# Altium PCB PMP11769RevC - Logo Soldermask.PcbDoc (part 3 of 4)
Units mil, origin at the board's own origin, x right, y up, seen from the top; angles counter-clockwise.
Board outline 7800 x 8510 mil, 4 copper layers (Top, Inner Top, Inner Bottom, Bottom), stack 33.235 mil thick; 451 components, 226 nets, 1199 pads, 1742 vias.
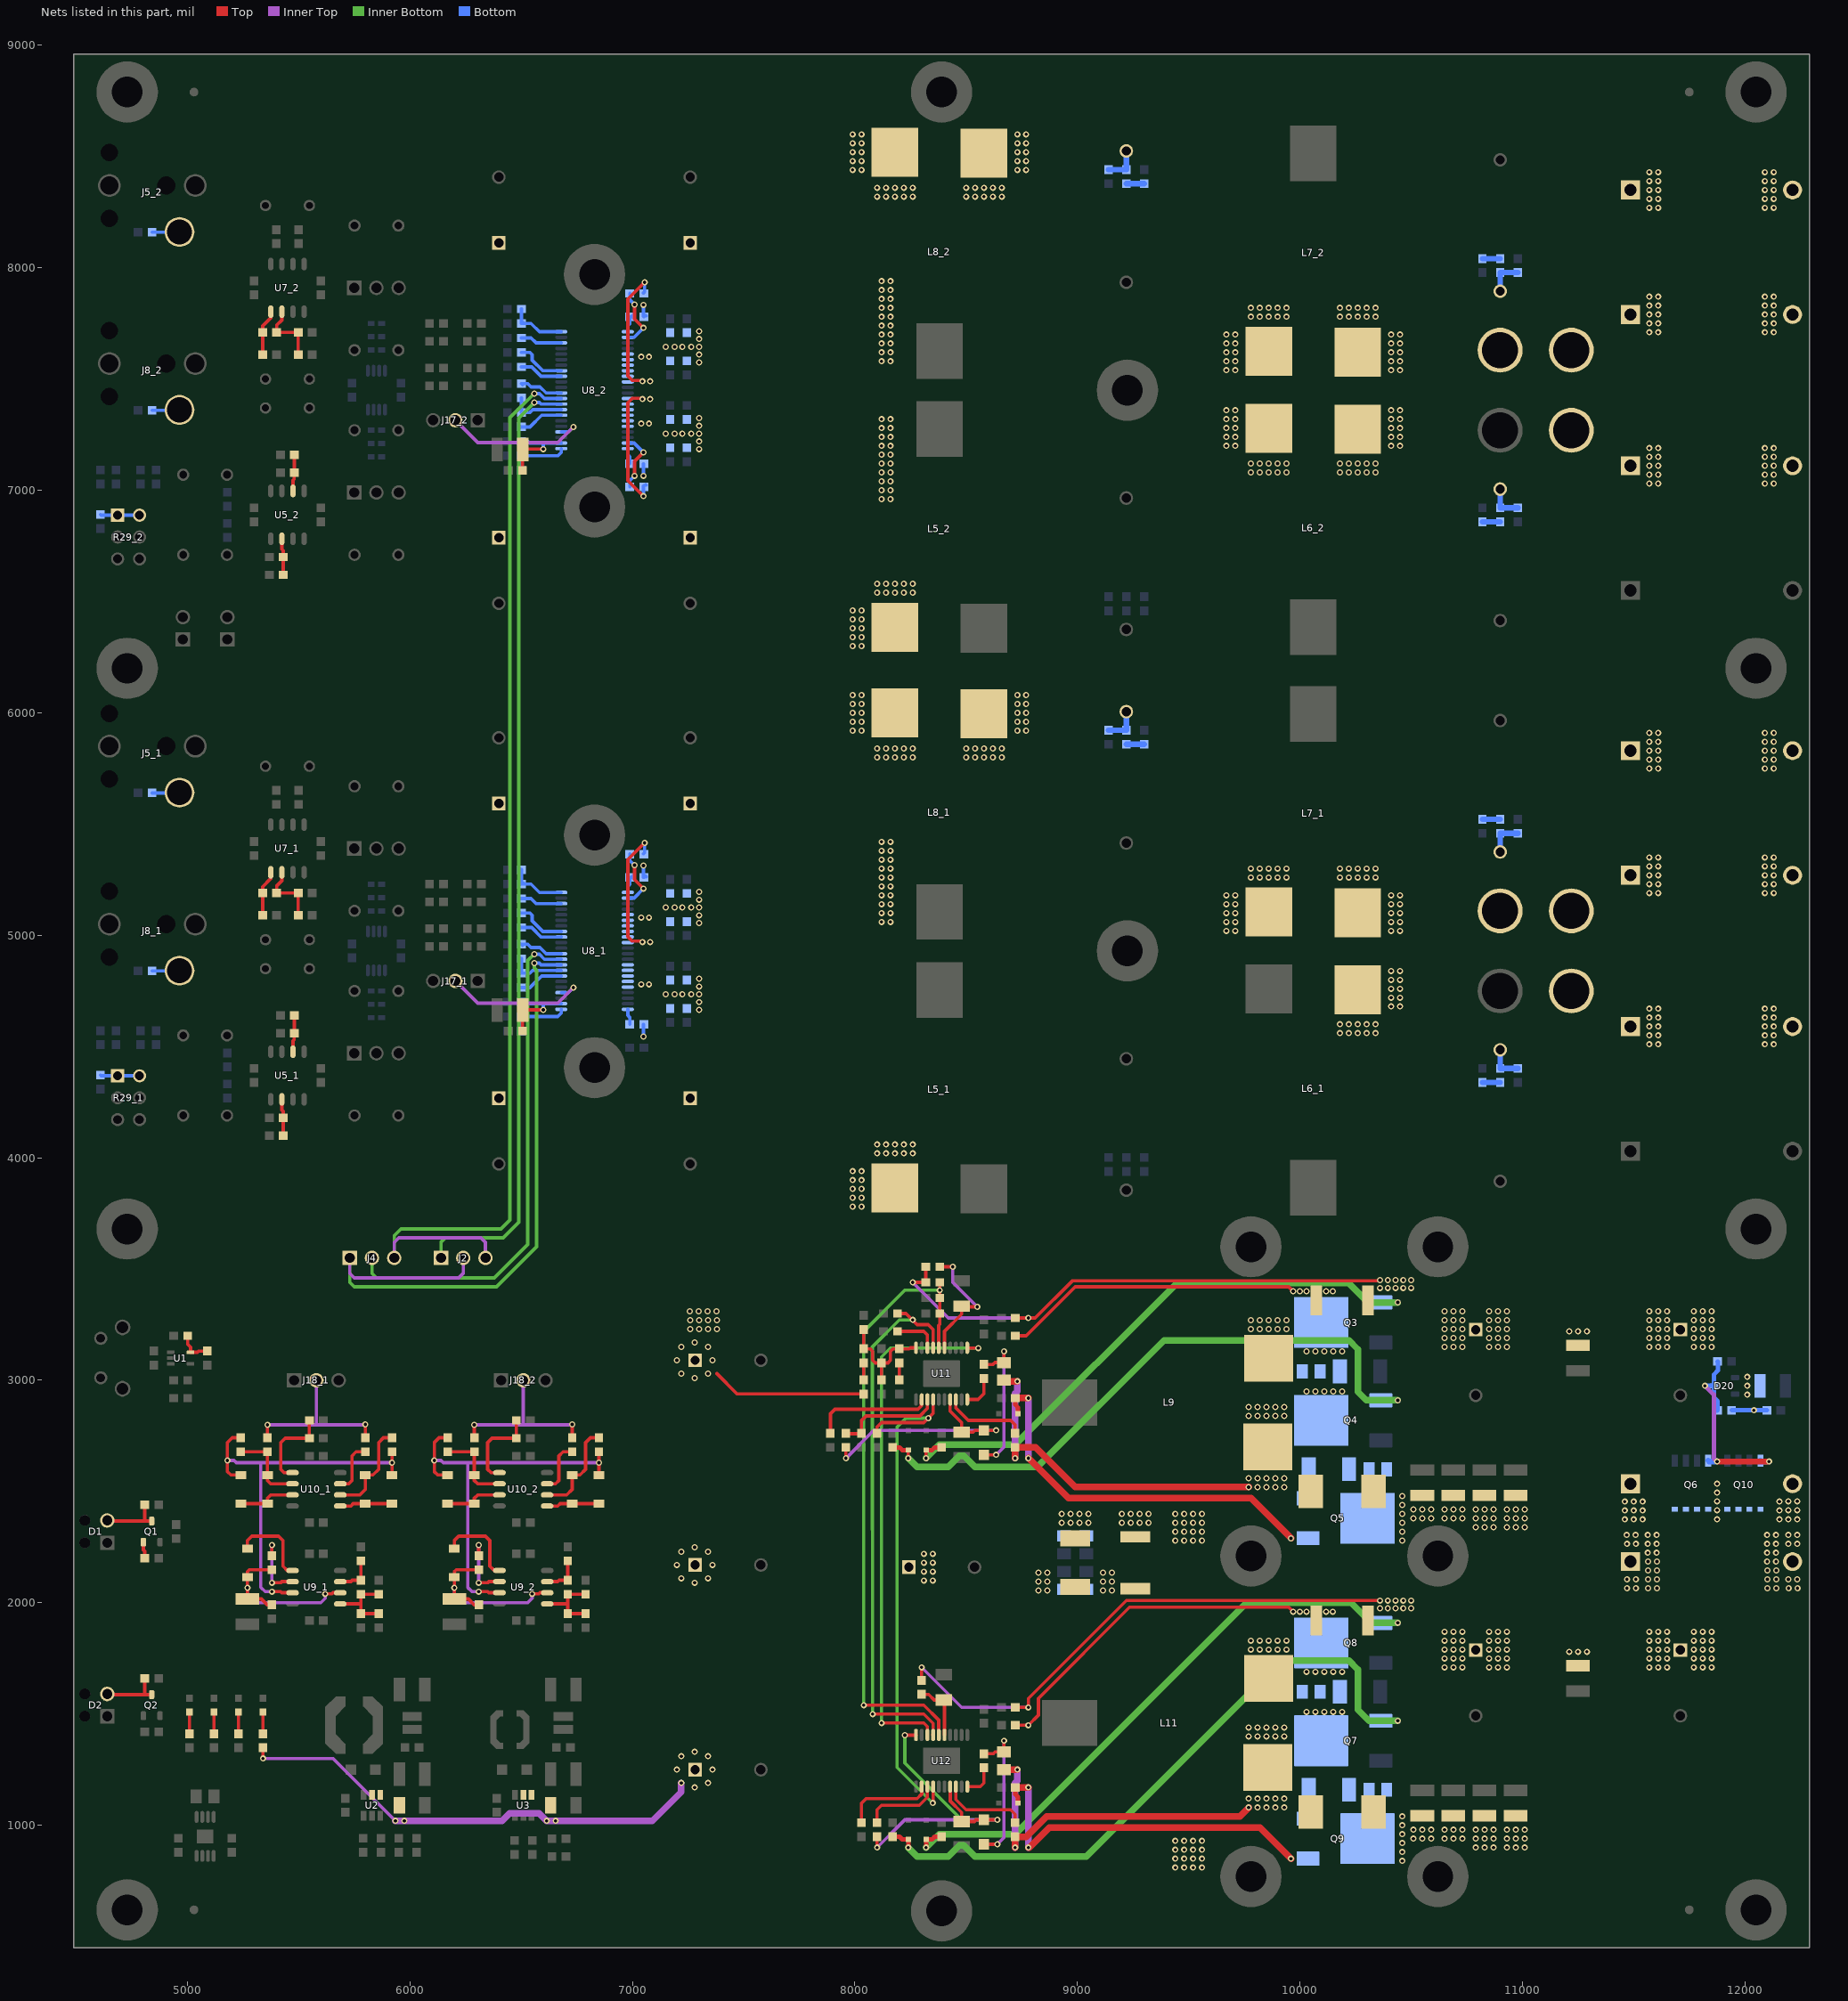
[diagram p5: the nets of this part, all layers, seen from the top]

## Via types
v1: diameter 28, hole 15, Top to Bottom, 1742 vias

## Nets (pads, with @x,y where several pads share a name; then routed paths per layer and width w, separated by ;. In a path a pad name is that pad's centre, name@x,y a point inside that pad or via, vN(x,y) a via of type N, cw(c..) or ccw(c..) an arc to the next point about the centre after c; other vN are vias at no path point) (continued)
NetC54_2_1: C54_2.1 U8_2.43 | length 268.5
  Top w15: v1(7010,7065) 7010,7130 v1(7050,7170)
  Bottom w15: U8_2.43@6979.61,7212.5 7007.5,7212.5 v1(7050,7170) ; C54_2.1@6988.5,7015 6988.5,7043.5 v1(7010,7065)
NetC54_2_2: C54_2.2 L6_2.2 U8_2.35 | length 576.3
  Top w15: v1(7050,6973.7) 6980,7043.7 6980,7393.7 7000,7413.7 v1@7050,7413.7
  Bottom w15: v1(7050,6973.7) 7050,7018.5 C54_2.2@7051.5,7020 ; C54_2.2@7060,7025.2 C54_2.2@7061.5,7023.7
  other v1: 8120,6960 8160,6960 8120,7000 8160,7000 8120,7040 8160,7040 8120,7080 8160,7080 9780,7080 9820,7080 9860,7080 9900,7080 9940,7080 8120,7120 8160,7120 9780,7120 9820,7120 9860,7120 9900,7120 9940,7120 8120,7160 8160,7160 8120,7200 8160,7200 9670,7200 9710,7200 8120,7240 8160,7240 9670,7240 9710,7240 8120,7280 8160,7280 9670,7280 9710,7280 8120,7320 8160,7320 9670,7320 9710,7320 9670,7360 9710,7360 7045,7410 7080,7410
NetC55_1_1: C55_1.1 U8_1.44 | length 71.2
  Bottom w15: U8_1.44@6979.61,4667.5 6979.61,4640.39 6988.5,4631.5 C55_1.1@6988.5,4600
NetC55_1_2: C55_1.2 L5_1.1 U8_1.39 U8_1.40 | length 53.5
  Bottom w15: v1(7050,4545) C55_1.2@7050,4598.5
  other v1: 7990,3780 8030,3780 7990,3820 8030,3820 7990,3860 8030,3860 7990,3900 8030,3900 7990,3940 8030,3940 8100,4020 8140,4020 8180,4020 8220,4020 8260,4020 8100,4060 8140,4060 8180,4060 8220,4060 8260,4060 7040,4780 7075,4780
NetC55_2_1: C55_2.1 U8_2.44 | length 71.2
  Bottom w15: U8_2.44@6979.61,7187.5 6979.61,7160.39 6988.5,7151.5 C55_2.1@6988.5,7120
NetC55_2_2: C55_2.2 L5_2.1 U8_2.39 U8_2.40 | length 53.5
  Bottom w15: v1(7050,7065) C55_2.2@7050,7118.5
  other v1: 7990,6300 8030,6300 7990,6340 8030,6340 7990,6380 8030,6380 7990,6420 8030,6420 7990,6460 8030,6460 8100,6540 8140,6540 8180,6540 8220,6540 8260,6540 8100,6580 8140,6580 8180,6580 8220,6580 8260,6580 7040,7300 7075,7300
NetC58_1_1: C58_1.1 U8_1.11 | length 203.6
  Bottom w15: C58_1.1@6506.5,4955 C58_1.1@6501.5,4960 6530.02,4960 6545.02,4945 6585,4945 6612.5,4917.5 U8_1.11@6680.39,4917.5
NetC58_2_1: C58_2.1 U8_2.11 | length 203.6
  Bottom w15: C58_2.1@6506.5,7475 C58_2.1@6501.5,7480 6530.02,7480 6545.02,7465 6585,7465 6612.5,7437.5 U8_2.11@6680.39,7437.5
NetC59_1_1: C59_1.1 U8_1.14 | length 196.9
  Bottom w15: C59_1.1@6501.5,5035 6547.65,5035 6590.15,4992.5 U8_1.14@6680.39,4992.5 U8_1.14@6680.39,4992.87
NetC59_2_1: C59_2.1 U8_2.14 | length 196.9
  Bottom w15: C59_2.1@6501.5,7555 6547.65,7555 6590.15,7512.5 U8_2.14@6680.39,7512.5 U8_2.14@6680.39,7512.87
NetC60_1_2: C60_1.2 R46_1.1 U8_1.1 | length 271.1
  Bottom w15: R46_1.1@6501.5,4570 C60_1.2@6501.5,4635 C60_1.2@6511.5,4635 ; C60_1.2@6511.5,4638.7 C60_1.2@6511.5,4635 ; U8_1.1@6680.39,4667.5 6680.39,4650.39 6665,4635 C60_1.2@6511.5,4635
NetC60_2_2: C60_2.2 R46_2.1 U8_2.1 | length 271.1
  Bottom w15: R46_2.1@6501.5,7090 C60_2.2@6501.5,7155 C60_2.2@6511.5,7155 ; C60_2.2@6511.5,7158.7 C60_2.2@6511.5,7155 ; U8_2.1@6680.39,7187.5 6680.39,7170.39 6665,7155 C60_2.2@6511.5,7155
NetC61_1_1: C61_1.1 C62_1.1 C63_1.1 J11_1.1 J12_1.1 J12_1.2 L6_1.1 | length 163.8
  Bottom w25: C62_1.1@10900,4485.28 C61_1.1@10900,4401.5 C63_1.1@10980,4401.5
  other v1: 11570,4510 11610,4510 12090,4510 12130,4510 11570,4550 11610,4550 12090,4550 12130,4550 10180,4560 10220,4560 10260,4560 10300,4560 10340,4560 11570,4590 11610,4590 12090,4590 12130,4590 10180,4600 10220,4600 10260,4600 10300,4600 10340,4600 11570,4630 11610,4630 12090,4630 12130,4630 11570,4670 11610,4670 12090,4670 12130,4670 10410,4680 10450,4680 10410,4720 10450,4720 10410,4760 10450,4760 10410,4800 10450,4800 10410,4840 10450,4840
NetC61_1_2: C61_1.2 R47_1.2 | length 80
  Bottom w25: R47_1.2@10820,4338.5 C61_1.2@10900,4338.5
NetC61_2_1: C61_2.1 C62_2.1 C63_2.1 J11_2.1 J12_2.1 J12_2.2 L6_2.1 | length 163.8
  Bottom w25: C62_2.1@10900,7005.28 C61_2.1@10900,6921.5 C63_2.1@10980,6921.5
  other v1: 11570,7030 11610,7030 12090,7030 12130,7030 11570,7070 11610,7070 12090,7070 12130,7070 10180,7080 10220,7080 10260,7080 10300,7080 10340,7080 11570,7110 11610,7110 12090,7110 12130,7110 10180,7120 10220,7120 10260,7120 10300,7120 10340,7120 11570,7150 11610,7150 12090,7150 12130,7150 11570,7190 11610,7190 12090,7190 12130,7190 10410,7200 10450,7200 10410,7240 10450,7240 10410,7280 10450,7280 10410,7320 10450,7320 10410,7360 10450,7360
NetC61_2_2: C61_2.2 R47_2.2 | length 80
  Bottom w25: R47_2.2@10820,6858.5 C61_2.2@10900,6858.5
NetC64_1_1: C64_1.1 L7_1.1 U8_1.32 | length 581.2
  Top w15: v1@7050,4973.7 7000,4973.7 6980,4993.7 6980,5340 v1(7055,5415)
  Bottom w15: C64_1.1@7050,5366.5 7055,5371.5 v1(7055,5415)
  other v1: 7045,4970 7080,4970 9670,5020 9710,5020 8120,5060 8160,5060 9670,5060 9710,5060 8120,5100 8160,5100 9670,5100 9710,5100 8120,5140 8160,5140 9670,5140 9710,5140 8120,5180 8160,5180 9670,5180 9710,5180 8120,5220 8160,5220 8120,5260 8160,5260 9780,5260 9820,5260 9860,5260 9900,5260 9940,5260 8120,5300 8160,5300 9780,5300 9820,5300 9860,5300 9900,5300 9940,5300 8120,5340 8160,5340 8120,5380 8160,5380 8120,5420 8160,5420
NetC64_1_2: C64_1.2 U8_1.24 | length 268.5
  Top w15: v1(7010,5315) 7010,5250 v1(7050,5210)
  Bottom w15: U8_1.24@6979.61,5167.5 7007.5,5167.5 v1(7050,5210) ; C64_1.2@6988.5,5365 6988.5,5336.5 v1(7010,5315)
NetC64_2_1: C64_2.1 L7_2.1 U8_2.32 | length 581.2
  Top w15: v1@7050,7493.7 7000,7493.7 6980,7513.7 6980,7860 v1(7055,7935)
  Bottom w15: C64_2.1@7050,7886.5 7055,7891.5 v1(7055,7935)
  other v1: 7045,7490 7080,7490 9670,7540 9710,7540 8120,7580 8160,7580 9670,7580 9710,7580 8120,7620 8160,7620 9670,7620 9710,7620 8120,7660 8160,7660 9670,7660 9710,7660 8120,7700 8160,7700 9670,7700 9710,7700 8120,7740 8160,7740 8120,7780 8160,7780 9780,7780 9820,7780 9860,7780 9900,7780 9940,7780 8120,7820 8160,7820 9780,7820 9820,7820 9860,7820 9900,7820 9940,7820 8120,7860 8160,7860 8120,7900 8160,7900 8120,7940 8160,7940
NetC64_2_2: C64_2.2 U8_2.24 | length 268.5
  Top w15: v1(7010,7835) 7010,7770 v1(7050,7730)
  Bottom w15: U8_2.24@6979.61,7687.5 7007.5,7687.5 v1(7050,7730) ; C64_2.2@6988.5,7885 6988.5,7856.5 v1(7010,7835)
NetC65_1_1: C65_1.1 L8_1.2 U8_1.27 U8_1.28 | length 56.4
  Bottom w15: v1(7050,5313.7) 7050,5261.5 C65_1.1@7051.5,5260 ; C65_1.1@7060,5265.2 C65_1.1@7061.5,5263.7
  other v1: 7040,5080 7075,5080 8100,5800 8140,5800 8180,5800 8220,5800 8260,5800 8100,5840 8140,5840 8180,5840 8220,5840 8260,5840 7990,5920 8030,5920 7990,5960 8030,5960 7990,6000 8030,6000 7990,6040 8030,6040 7990,6080 8030,6080
NetC65_1_2: C65_1.2 U8_1.23 | length 83.8
  Bottom w15: U8_1.23@6979.61,5192.5 6979.61,5219.61 6988.5,5228.5 C65_1.2@6988.5,5260 ; C65_1.2@6989.61,5254.8 C65_1.2@6998.5,5263.7
NetC65_2_1: C65_2.1 L8_2.2 U8_2.27 U8_2.28 | length 56.4
  Bottom w15: v1(7050,7833.7) 7050,7781.5 C65_2.1@7051.5,7780 ; C65_2.1@7060,7785.2 C65_2.1@7061.5,7783.7
  other v1: 7040,7600 7075,7600 8100,8320 8140,8320 8180,8320 8220,8320 8260,8320 8100,8360 8140,8360 8180,8360 8220,8360 8260,8360 7990,8440 8030,8440 7990,8480 8030,8480 7990,8520 8030,8520 7990,8560 8030,8560 7990,8600 8030,8600
NetC65_2_2: C65_2.2 U8_2.23 | length 83.8
  Bottom w15: U8_2.23@6979.61,7712.5 6979.61,7739.61 6988.5,7748.5 C65_2.2@6988.5,7780 ; C65_2.2@6989.61,7774.8 C65_2.2@6998.5,7783.7
NetC66_1_2: C66_1.2 C67_1.1 R48_1.1 U8_1.2 | length 396.8
  Top w15: R48_1.1@6506.5,4570 6507.09,4570.59 C67_1.1@6507.09,4663.54 6508.54,4665 v1(6600,4665)
  Bottom w15: C66_1.2@6501.5,4700 6531.02,4700 6538.52,4692.5 6600,4692.5 ; v1(6600,4665) 6600,4692.5 ; U8_1.2@6680.39,4692.5 6600,4692.5
NetC66_2_2: C66_2.2 C67_2.1 R48_2.1 U8_2.2 | length 396.8
  Top w15: R48_2.1@6506.5,7090 6507.09,7090.59 C67_2.1@6507.09,7183.54 6508.54,7185 v1(6600,7185)
  Bottom w15: C66_2.2@6501.5,7220 6531.02,7220 6538.52,7212.5 6600,7212.5 ; v1(6600,7185) 6600,7212.5 ; U8_2.2@6680.39,7212.5 6600,7212.5
NetC68_1_1: C68_1.1 C69_1.1 C70_1.1 J13_1.1 J13_1.2 J14_1.1 L7_1.2 | length 163.8
  Bottom w25: C69_1.1@10900,5374.72 C68_1.1@10900,5458.5 C70_1.1@10980,5458.5
  other v1: 10410,5020 10450,5020 10410,5060 10450,5060 10410,5100 10450,5100 10410,5140 10450,5140 10410,5180 10450,5180 11570,5190 11610,5190 12090,5190 12130,5190 11570,5230 11610,5230 12090,5230 12130,5230 10180,5260 10220,5260 10260,5260 10300,5260 10340,5260 11570,5270 11610,5270 12090,5270 12130,5270 10180,5300 10220,5300 10260,5300 10300,5300 10340,5300 11570,5310 11610,5310 12090,5310 12130,5310 11570,5350 11610,5350 12090,5350 12130,5350
NetC68_1_2: C68_1.2 R50_1.2 | length 80
  Bottom w25: R50_1.2@10820,5521.5 C68_1.2@10900,5521.5
NetC68_2_1: C68_2.1 C69_2.1 C70_2.1 J13_2.1 J13_2.2 J14_2.1 L7_2.2 | length 163.8
  Bottom w25: C69_2.1@10900,7894.72 C68_2.1@10900,7978.5 C70_2.1@10980,7978.5
  other v1: 10410,7540 10450,7540 10410,7580 10450,7580 10410,7620 10450,7620 10410,7660 10450,7660 10410,7700 10450,7700 11570,7710 11610,7710 12090,7710 12130,7710 11570,7750 11610,7750 12090,7750 12130,7750 10180,7780 10220,7780 10260,7780 10300,7780 10340,7780 11570,7790 11610,7790 12090,7790 12130,7790 10180,7820 10220,7820 10260,7820 10300,7820 10340,7820 11570,7830 11610,7830 12090,7830 12130,7830 11570,7870 11610,7870 12090,7870 12130,7870
NetC68_2_2: C68_2.2 R50_2.2 | length 80
  Bottom w25: R50_2.2@10820,8041.5 C68_2.2@10900,8041.5
NetC71_1_2: C71_1.2 U8_1.15 | length 227.7
  Bottom w15: C71_1.2@6501.5,5100 6540,5100 6550,5090 6550,5065 6597.5,5017.5 U8_1.15@6680.39,5017.5
NetC71_2_2: C71_2.2 U8_2.15 | length 227.7
  Bottom w15: C71_2.2@6501.5,7620 6540,7620 6550,7610 6550,7585 6597.5,7537.5 U8_2.15@6680.39,7537.5
NetC72_1_2: C72_1.2 R51_1.1 U8_1.22 | length 259.4
  Bottom w15: R51_1.1@6501.5,5295 C72_1.2@6501.5,5230 6545,5230 6582.5,5192.5 U8_1.22@6680.39,5192.5
NetC72_2_2: C72_2.2 R51_2.1 U8_2.22 | length 259.4
  Bottom w15: R51_2.1@6501.5,7815 C72_2.2@6501.5,7750 6545,7750 6582.5,7712.5 U8_2.22@6680.39,7712.5
NetC73_1_1: C73_1.1 U8_1.20 | length 188.2
  Bottom w15: C73_1.1@6501.5,5165 6545,5165 6567.5,5142.5 U8_1.20@6680.39,5142.5
NetC73_2_1: C73_2.1 U8_2.20 | length 188.2
  Bottom w15: C73_2.1@6501.5,7685 6545,7685 6567.5,7662.5 U8_2.20@6680.39,7662.5
NetC74_1_1: C74_1.1 C75_1.1 C76_1.1 J15_1.1 J16_1.1 J16_1.2 L8_1.1 | length 163.8
  Bottom w25: C76_1.1@9140,5921.5 C74_1.1@9220,5921.5 C75_1.1@9220,6005.28
  other v1: 11570,5750 11610,5750 12090,5750 12130,5750 11570,5790 11610,5790 12090,5790 12130,5790 8500,5800 8540,5800 8580,5800 8620,5800 8660,5800 11570,5830 11610,5830 12090,5830 12130,5830 8500,5840 8540,5840 8580,5840 8620,5840 8660,5840 11570,5870 11610,5870 12090,5870 12130,5870 11570,5910 11610,5910 12090,5910 12130,5910 8730,5920 8770,5920 8730,5960 8770,5960 8730,6000 8770,6000 8730,6040 8770,6040 8730,6080 8770,6080
NetC74_1_2: C74_1.2 R52_1.2 | length 80
  Bottom w25: C74_1.2@9220,5858.5 R52_1.2@9300,5858.5
NetC74_2_1: C74_2.1 C75_2.1 C76_2.1 J15_2.1 J16_2.1 J16_2.2 L8_2.1 | length 163.8
  Bottom w25: C76_2.1@9140,8441.5 C74_2.1@9220,8441.5 C75_2.1@9220,8525.28
  other v1: 11570,8270 11610,8270 12090,8270 12130,8270 11570,8310 11610,8310 12090,8310 12130,8310 8500,8320 8540,8320 8580,8320 8620,8320 8660,8320 11570,8350 11610,8350 12090,8350 12130,8350 8500,8360 8540,8360 8580,8360 8620,8360 8660,8360 11570,8390 11610,8390 12090,8390 12130,8390 11570,8430 11610,8430 12090,8430 12130,8430 8730,8440 8770,8440 8730,8480 8770,8480 8730,8520 8770,8520 8730,8560 8770,8560 8730,8600 8770,8600
NetC74_2_2: C74_2.2 R52_2.2 | length 80
  Bottom w25: C74_2.2@9220,8378.5 R52_2.2@9300,8378.5
NetC79_1_1: C79_1.1 D11_1.1 R56_1.1 R60_1.2 U9_1.6 | length 862.5
  Top w15: R60_1.2@5380,1991.5 5358.5,1991.5 5332.91,2017.09 C79_1.1@5270,2017.09 v1(5270,2067.22) D11_1.1@5270,2115.53 5270,2140 5278.5,2148.5 R56_1.1@5380,2148.5 ; v1(5620,2040) 5650,2040 5655,2045 U9_1.6@5687.28,2045
  Inner Top w15: v1(5270,2067.22) 5270,2020 5290,2000 5600,2000 5620,2020 v1(5620,2040) v1@5618.33,2041.67
NetC79_2_1: C79_2.1 D11_2.1 R56_2.1 R60_2.2 U9_2.6 | length 862.5
  Top w15: R60_2.2@6310,1991.5 6288.5,1991.5 6262.91,2017.09 C79_2.1@6200,2017.09 v1(6200,2067.22) D11_2.1@6200,2115.53 6200,2140 6208.5,2148.5 R56_2.1@6310,2148.5 ; v1(6550,2040) 6580,2040 6585,2045 U9_2.6@6617.28,2045
  Inner Top w15: v1(6200,2067.22) 6200,2020 6220,2000 6530,2000 6550,2020 v1(6550,2040) v1@6548.33,2041.67
NetC81_1_2: C81_1.2 R57_1.1 R61_1.1 R62_1.1 U9_1.5 | length 339.7
  Top w15: U9_1.5@5687.28,1995 5780,1995 ; C81_1.2@5860,1951.5 R61_1.1@5780,1951.5 5780,1995 ; R57_1.1@5860,2038.5 R62_1.1@5780,2038.5 5780,1995
NetC81_2_2: C81_2.2 R57_2.1 R61_2.1 R62_2.1 U9_2.5 | length 339.7
  Top w15: U9_2.5@6617.28,1995 6710,1995 ; C81_2.2@6790,1951.5 R61_2.1@6710,1951.5 6710,1995 ; R57_2.1@6790,2038.5 R62_2.1@6710,2038.5 6710,1995
NetC85_2: C85.2 R74.1 | length 77
  Top w15: C85.2@8200,3001.5 R74.1@8200,3078.5
NetC88_1: C88.1 D14.1 R72.1 | length 683.1
  Top w15: D14.1@8580,2664.88 8580.12,2665 v1(8635,2665) ; R72.1@8580,3071.5 8621.5,3071.5 8630,3080 C88.1@8670,3080 v1(8670,3130)
  Inner Top w15: v1(8635,2665) 8670,2700 v1@8670,3135
NetC89_1: C89.1 D15.1 R73.1 | length 681.3
  Top w15: D15.1@8580,914.88 8580.12,915 v1(8640,915) ; R73.1@8580,1321.5 8621.5,1321.5 8630,1330 C89.1@8670,1330 v1(8670,1380)
  Inner Top w15: v1(8640,915) 8670.37,945.37 8670.37,1379.63 v1(8670,1380)
NetC90_2: C90.2 R74.2 R78.1 R85.2 R86.2 U11.10 | length 490.3
  Top w15: R86.2@8040,3228.5 R78.1@8040,3141.5 8068.5,3141.5 8080,3130 8080,3090 8091.5,3078.5 R85.2@8120,3078.5 ; C90.2@8120,3001.5 R85.2@8120,3078.5 ; 8243.5,3141.5 8171.5,3141.5 8160,3130 8160,3090 8148.5,3078.5 R85.2@8120,3078.5 ; 8251.14,3146.14 U11.10@8274.84,3146.14
NetC92_2: C92.2 R69.1 U11.5 | length 574.3
  Top w15: R69.1@8381.5,3510 v1(8440,3510) ; U11.5@8402.8,3146.14 8402.8,3219.65 8402.48,3219.96 8480,3297.48 C92.2@8480,3332.91 8482.91,3330 v1(8550,3330)
  Inner Top w15: v1(8440,3510) 8440,3440 v1(8550,3330)
NetC93_2: C93.2 R71.1 U12.5 | length 258.5
  Top w15: R71.1@8300,1588.5 8331.5,1588.5 8357.09,1562.91 C93.2@8400,1562.91 ; C93.2@8400,1552.91 8402.8,1550.12 U12.5@8402.8,1406.14
NetC95_1: C95.1 R87.2
NetC95_2: C95.2 C99.1 C100.1 C102.1 C103.1 C107.2 C111.2 C115.2 C119.1 C120.1 C122.1 C123.1 D16.1 D21.1 L10.1 Q5.4 Q9.4 R96.1
  other v1: 9440,810 9480,810 9520,810 9560,810 10460,840 9440,850 9480,850 9520,850 9560,850 10460,880 9440,890 9480,890 9520,890 9560,890 10790,900 10830,900 10870,900 10930,900 10970,900 11010,900 10460,920 9440,930 9480,930 9520,930 9560,930 10510,940 10550,940 10590,940 10650,940 10690,940 10730,940 10790,940 10830,940 10870,940 10930,940 10970,940 11010,940 10460,960 10510,980 10550,980 10590,980 10650,980 10690,980 10730,980 10790,980 10830,980 10870,980 10930,980 10970,980 11010,980 10460,1000 10460,1040 9440,2280 9480,2280 9520,2280 9560,2280 10460,2280 9440,2320 9480,2320 9520,2320 9560,2320 10460,2320 10790,2340 10830,2340 10870,2340 10930,2340 10970,2340 11010,2340 8930,2360 8970,2360 9010,2360 9050,2360 9200,2360 9240,2360 9280,2360 9320,2360 9440,2360 9480,2360 9520,2360 9560,2360 10460,2360 10510,2380 10550,2380 10590,2380 10650,2380 10690,2380 10730,2380 10790,2380 10830,2380 10870,2380 10930,2380 10970,2380 11010,2380 8930,2400 8970,2400 9010,2400 9050,2400 9200,2400 9240,2400 9280,2400 9320,2400 9440,2400 9480,2400 9520,2400 9560,2400 10460,2400 10510,2420 10550,2420 10590,2420 10650,2420 10690,2420 10730,2420 10790,2420 10830,2420 10870,2420 10930,2420 10970,2420 11010,2420 10460,2440 10460,2480
NetC96_2: C96.2 R90.2
NetC106_2: C106.2 D20.3 Q6.4 Q10.4 R89.2 | length 958.2
  Top w25: v1(11875,2635) v1(12108.5,2635)
  Inner Top w20: v1(11820,2975) 11860,2935 11860,2650 v1(11875,2635)
  Bottom w20: v1(11820,2975) D20.3@11861.26,2975 ; R89.2@11875,2863 R89.2@11877,2865 11877,2906.5 11861.26,2922.24 D20.3@11861.26,2975 ; C106.2@11877,3085 11878.5,3083.5 11878.5,3043.9 11861.26,3026.65 D20.3@11861.26,2975
  Bottom w25: Q6.4@11835,2639.3 11839.3,2635 v1(11875,2635) ; Q10.4@12068.5,2639.3 12072.8,2635 v1(12108.5,2635)
NetC111_1: C111.1 R97.2
NetC116_2: C116.2 R99.2
NetD1_2: D1.2 Q1.3 R2.1 | length 274.4
  Top w15: D1.2@4640.2,2370.2 4643.15,2367.24 4810,2367.24 ; R2.1@4808.5,2440 4808.5,2368.74 4810,2367.24 ; Q1.3@4840,2367.24 4810,2367.24
NetD2_2: D2.2 Q2.3 R8.1 | length 274.4
  Top w15: D2.2@4640.2,1590.2 4643.15,1587.24 4810,1587.24 ; R8.1@4808.5,1660 4808.5,1588.74 4810,1587.24 ; Q2.3@4840,1587.24 4810,1587.24
NetD4_2: D4.2 R12.1 | length 97
  Top w15: R12.1@5340,1411.5 D4.2@5340,1508.5
NetD5_2: D5.2 R13.1 | length 97
  Top w15: R13.1@5230,1411.5 D5.2@5230,1508.5
NetD6_1: D6.1 R14.1 | length 97
  Top w15: R14.1@5120,1411.5 D6.1@5120,1508.5
NetD7_2: D7.2 R15.1 | length 97
  Top w15: R15.1@5010,1411.5 D7.2@5010,1508.5
NetD9_1_1: D9_1.1 D10_1.2 U10_1.1 | length 237.1
  Top w15: U10_1.1@5687.28,2435 5735,2435 5745.53,2445.53 D9_1.1@5800,2445.53 D10_1.2@5920,2445.53
NetD9_1_2: D9_1.2 R55_1.2 U10_1.2 | length 447
  Top w15: U10_1.2@5687.28,2485 5774.99,2485 5800,2510.01 D9_1.2@5800,2574.47 5834.47,2574.47 5860,2600 5860,2720 5881.5,2741.5 R55_1.2@5920,2741.5
NetD9_2_1: D9_2.1 D10_2.2 U10_2.1 | length 237.1
  Top w15: U10_2.1@6617.28,2435 6665,2435 6675.53,2445.53 D9_2.1@6730,2445.53 D10_2.2@6850,2445.53
NetD9_2_2: D9_2.2 R55_2.2 U10_2.2 | length 447
  Top w15: U10_2.2@6617.28,2485 6704.99,2485 6730,2510.01 D9_2.2@6730,2574.47 6764.47,2574.47 6790,2600 6790,2720 6811.5,2741.5 R55_2.2@6850,2741.5
NetD10_1_1: D10_1.1 D13_1.1 R55_1.1 R63_1.1 U9_1.3 | length 1826.5
  Top w15: D13_1.1@5240,2574.47 5195.53,2574.47 5180,2590 v1(5180,2640) 5180,2720 5201.5,2741.5 R63_1.1@5240,2741.5 ; v1(5380,2050) 5420,2050 5425,2045 U9_1.3@5472.72,2045 ; D10_1.1@5920,2574.47 v1(5920,2630) R55_1.1@5920,2678.5
  Inner Top w15: v1(5180,2640) 5210,2640 5220.37,2629.63 5330,2629.63 ; v1(5380,2050) 5350,2050 5330,2070 5330,2629.63 ; v1(5920,2630) 5919.63,2629.63 5330,2629.63
NetD10_2_1: D10_2.1 D13_2.1 R55_2.1 R63_2.1 U9_2.3 | length 1826.5
  Top w15: D13_2.1@6170,2574.47 6125.53,2574.47 6110,2590 v1(6110,2640) 6110,2720 6131.5,2741.5 R63_2.1@6170,2741.5 ; v1(6310,2050) 6350,2050 6355,2045 U9_2.3@6402.72,2045 ; D10_2.1@6850,2574.47 v1(6850,2630) R55_2.1@6850,2678.5
  Inner Top w15: v1(6110,2640) 6140,2640 6150.37,2629.63 6260,2629.63 ; v1(6310,2050) 6280,2050 6260,2070 6260,2629.63 ; v1(6850,2630) 6849.63,2629.63 6260,2629.63
NetD11_1_2: D11_1.2 U9_1.1 | length 378.5
  Top w15: D11_1.2@5270,2244.47 5270,2280 5290,2300 5410,2300 5430,2280 5430,2164.33 5449.33,2145 U9_1.1@5472.72,2145
NetD11_2_2: D11_2.2 U9_2.1 | length 378.5
  Top w15: D11_2.2@6200,2244.47 6200,2280 6220,2300 6340,2300 6360,2280 6360,2164.33 6379.33,2145 U9_2.1@6402.72,2145
NetD12_1_1: D12_1.1 D13_1.2 U10_1.7 | length 263.4
  Top w15: D13_1.2@5240,2445.53 D12_1.1@5360,2445.53 5360,2470 5375,2485 U10_1.7@5472.72,2485
NetD12_1_2: D12_1.2 R63_1.2 R64_1.2 U10_1.6 | length 367.4
  Top w15: R63_1.2@5240,2678.5 R64_1.2@5360,2678.5 D12_1.2@5360,2574.46 5360,2550 5375,2535 U10_1.6@5472.72,2535
NetD12_2_1: D12_2.1 D13_2.2 U10_2.7 | length 263.4
  Top w15: D13_2.2@6170,2445.53 D12_2.1@6290,2445.53 6290,2470 6305,2485 U10_2.7@6402.72,2485
NetD12_2_2: D12_2.2 R63_2.2 R64_2.2 U10_2.6 | length 367.4
  Top w15: R63_2.2@6170,2678.5 R64_2.2@6290,2678.5 D12_2.2@6290,2574.46 6290,2550 6305,2535 U10_2.6@6402.72,2535
NetD17_2: D17.2 Q3.1 R93.2 | length 2594.3
  Top w15: v1(8320,2650) D17.2@8320,2686.69
  Top w20: D17.2@8320,2686.69 8347.19,2686.69 8359,2698.5 R93.2@8390,2698.5
  Inner Bottom w30: v1(8320,2650) 8380,2710 8720,2710 9447.87,3437.87 10218.9,3437.87 10306.77,3350 v1(10440,3350)
NetD18_2: D18.2 Q4.1 R94.2 | length 2829.3
  Top w15: v1(8240,2650) D18.2@8240,2686.69
  Top w20: R94.2@8170,2698.5 8201,2698.5 8212.81,2686.69 D18.2@8240,2686.69
  Inner Bottom w30: v1(8240,2650) 8280,2610 8420,2610 8470,2660 8490,2660 8540,2610 8820,2610 9390,3180 10220,3180 10260,3140 10260,2949.13 10299.13,2910 v1(10440,2910)
NetD19_2: D19.2 Q5.1 R95.2 | length 1712.5
  Top w20: R95.2@8721.5,2920 8721.5,2889 8733.31,2877.19 D19.2@8733.31,2850
  Top w30: R95.2@8721.5,2920 v1(8780,2920) ; v1(8780,2650) 8960,2470 9780,2470 v1(9960,2290)
  Inner Top w30: v1@8780,2660 v1@8780,2910
NetD22_2: D22.2 Q7.1 R102.2 | length 2951.4
  Top w20: R102.2@8170,948.5 8201,948.5 8212.81,936.69 D22.2@8240,936.69 v1(8240,900)
  Inner Bottom w30: v1(8240,900) 8280,860 8420,860 8470,910 8490,910 8540,860 9040,860 9920,1740 10220,1740 10260,1700 10260,1520 10310,1470 v1(10440,1470)
NetD23_2: D23.2 Q8.1 R103.2 | length 2724.5
  Top w20: v1(8320,900) D23.2@8320,936.69 8347.19,936.69 8359,948.5 R103.2@8390,948.5
  Inner Bottom w30: v1(8320,900) 8380,960 8720,960 9760,2000 10230,2000 10320,1910 v1(10440,1910)
NetD24_2: D24.2 Q9.1 R104.2 | length 1678.7
  Top w20: R104.2@8721.5,1170 8721.5,1139 8733.31,1127.19 D24.2@8733.31,1100
  Top w30: R104.2@8721.5,1170 v1(8780,1170) ; v1(8780,900) 8783.56,900 8873.56,990 9820,990 v1(9960,850)
  Inner Top w30: v1(8780,900) v1(8780,1170)
NetJ5_1_4: J5_1.4 R23_1.2 | length 124
  Bottom w15: R23_1.2@4841.5,5640 4963.62,5640 J5_1.4@4964.96,5641.34
NetJ5_2_4: J5_2.4 R23_2.2 | length 124
  Bottom w15: R23_2.2@4841.5,8160 4963.62,8160 J5_2.4@4964.96,8161.34
NetJ8_1_4: J8_1.4 R40_1.2 | length 124
  Bottom w15: R40_1.2@4841.5,4840 4963.62,4840 J8_1.4@4964.96,4841.34
NetJ8_2_4: J8_2.4 R40_2.2 | length 124
  Bottom w15: R40_2.2@4841.5,7360 4963.62,7360 J8_2.4@4964.96,7361.34
NetJ17_1_2: J17_1.2 U8_1.4 | length 664.3
  Inner Top w15: J17_1.2@6205,4795 6305,4695 6665,4695 v1(6735,4765)
  Bottom w15: U8_1.4@6680.39,4742.5 6712.5,4742.5 v1(6735,4765)
NetJ17_2_2: J17_2.2 U8_2.4 | length 664.3
  Inner Top w15: J17_2.2@6205,7315 6305,7215 6665,7215 v1(6735,7285)
  Bottom w15: U8_2.4@6680.39,7262.5 6712.5,7262.5 v1(6735,7285)
NetJ18_1_2: J18_1.2 R59_1.1 R64_1.1 | length 759.1
  Top w15: R64_1.1@5360,2741.5 v1(5360,2800) ; R59_1.1@5800,2741.5 v1(5800,2801.5)
  Inner Top w15: v1(5360,2800) 5580,2800 ; J18_1.2@5580,3000 5580,2800 ; v1(5800,2801.5) 5798.5,2800 5580,2800
NetJ18_2_2: J18_2.2 R59_2.1 R64_2.1 | length 759.1
  Top w15: R64_2.1@6290,2741.5 v1(6290,2800) ; R59_2.1@6730,2741.5 v1(6730,2801.5)
  Inner Top w15: v1(6290,2800) 6510,2800 ; J18_2.2@6510,3000 6510,2800 ; v1(6730,2801.5) 6728.5,2800 6510,2800
NetJ20_1: J20.1 J20.2 Q6.5 Q6.6 Q6.7 Q6.8 Q10.5 Q10.6 Q10.7 Q10.8
  other v1: 11460,2375 11500,2375 11540,2375 11875,2375 12155,2375 12195,2375 12235,2375 11460,2415 11500,2415 11540,2415 12155,2415 11875,2416.5 12195,2416.5 12235,2416.5 11460,2455 11500,2455 11540,2455 12155,2455 11875,2456.5 12195,2456.5 12235,2456.5 11875,2495 11875,2535
NetL9_2: L9.2 R88.2 R92.2 | length 1347.9
  Top w15: R92.2@8721.5,3200 8770,3200 8990,3420 9950,3420 v1(9970,3400)
  other v1: 9780,3230 9820,3230 9860,3230 9900,3230 9940,3230 9780,3270 9820,3270 9860,3270 9900,3270 9940,3270 10000,3400 10030,3400 10118,3400 10148,3400
NetL11_2: L11.2 R98.2 R101.2 | length 1510.5
  Top w15: R101.2@8721.5,1450 v1@8770,1450 ; v1(8780,1450) 8824.82,1494.82 8824.82,1570.31 9234.52,1980 9950,1980 v1(9970,1960)
  other v1: 9780,1790 9820,1790 9860,1790 9900,1790 9940,1790 9780,1830 9820,1830 9860,1830 9900,1830 9940,1830 10000,1960 10030,1960 10118,1960 10148,1960
NetQ1_1: Q1.1 R4.2 | length 75.2
  Top w15: Q1.1@4802.6,2272.76 4802.6,2237.4 4808.5,2231.5 R4.2@4808.5,2200
NetR5_1: R5.1 R6.2 U1.5 | length 157.9
  Top w15: R6.2@5001.5,3200 5001.5,3161.65 5014.29,3148.86 U1.5@5014.29,3125.59 5045.59,3125.59 5051.5,3131.5 R5.1@5090,3131.5
NetR25_1_1: R25_1.1 R28_1.2 R33_1.2 U7_1.2 | length 299.5
  Top w15: U7_1.2@5425,5282.72 5425,5245 5401.5,5221.5 R25_1.1@5401.5,5190 R33_1.2@5498.5,5190 R28_1.2@5498.5,5090
NetR25_1_2: R25_1.2 R35_1.1 U7_1.1 | length 207.8
  Top w15: R35_1.1@5338.5,5090 R25_1.2@5338.5,5190 5338.5,5218.5 5375,5255 U7_1.1@5375,5282.72
NetR25_2_1: R25_2.1 R28_2.2 R33_2.2 U7_2.2 | length 299.5
  Top w15: U7_2.2@5425,7802.72 5425,7765 5401.5,7741.5 R25_2.1@5401.5,7710 R33_2.2@5498.5,7710 R28_2.2@5498.5,7610
NetR25_2_2: R25_2.2 R35_2.1 U7_2.1 | length 207.8
  Top w15: R35_2.1@5338.5,7610 R25_2.2@5338.5,7710 5338.5,7738.5 5375,7775 U7_2.1@5375,7802.72
NetR29_1_1: R29_1.1 R29_1.1' R32_1.2 | length 176.5
  Bottom w15: R32_1.2@4610,4371.5 4613.07,4368.43 R29_1.1@4686.85,4368.43 R29_1.1'@4785.28,4368.43
NetR29_2_1: R29_2.1 R29_2.1' R32_2.2 | length 176.5
  Bottom w15: R32_2.2@4610,6891.5 4613.07,6888.43 R29_2.1@4686.85,6888.43 R29_2.1'@4785.28,6888.43
NetR30_1_1: R30_1.1 R31_1.1 U5_1.2 | length 165.4
  Top w15: U5_1.2@5425,4262.72 5425,4215 5431.5,4208.5 R31_1.1@5431.5,4180 R30_1.1@5431.5,4100
NetR30_2_1: R30_2.1 R31_2.1 U5_2.2 | length 165.4
  Top w15: U5_2.2@5425,6782.72 5425,6735 5431.5,6728.5 R31_2.1@5431.5,6700 R30_2.1@5431.5,6620
NetR43_1_1: R43_1.1 R44_1.1 U5_1.6 | length 165.4
  Top w15: U5_1.6@5475,4477.28 5475,4525 5480,4530 5480,4558.5 R44_1.1@5481.5,4560 R43_1.1@5481.5,4640
NetR43_2_1: R43_2.1 R44_2.1 U5_2.6 | length 165.4
  Top w15: U5_2.6@5475,6997.28 5475,7045 5480,7050 5480,7078.5 R44_2.1@5481.5,7080 R43_2.1@5481.5,7160
NetR49_1_2: R49_1.2 U8_1.7 | length 200.6
  Bottom w15: R49_1.2@6501.5,4765 6540,4765 6592.5,4817.5 U8_1.7@6680.39,4817.5
NetR49_2_2: R49_2.2 U8_2.7 | length 200.6
  Bottom w15: R49_2.2@6501.5,7285 6540,7285 6592.5,7337.5 U8_2.7@6680.39,7337.5
NetR53_1_2: R53_1.2 R54_1.2 U8_1.8 | length 249.1
  Bottom w15: R54_1.2@6501.5,4895 R53_1.2@6501.5,4830 6540,4830 6552.5,4842.5 U8_1.8@6680.39,4842.5
NetR53_2_2: R53_2.2 R54_2.2 U8_2.8 | length 249.1
  Bottom w15: R54_2.2@6501.5,7415 R53_2.2@6501.5,7350 6540,7350 6552.5,7362.5 U8_2.8@6680.39,7362.5
NetR56_1_2: R56_1.2 U9_1.2 | length 313.3
  Top w15: v1(5380,2090) 5420,2090 5425,2095 U9_1.2@5472.72,2095 ; R56_1.2@5380,2211.5 v1(5380,2260)
  Inner Top w15: v1(5380,2090) v1(5380,2260)
NetR56_2_2: R56_2.2 U9_2.2 | length 313.3
  Top w15: v1(6310,2090) 6350,2090 6355,2095 U9_2.2@6402.72,2095 ; R56_2.2@6310,2211.5 v1(6310,2260)
  Inner Top w15: v1(6310,2090) v1(6310,2260)
NetR58_1_1: R58_1.1 R62_1.2 U9_1.7 | length 182.4
  Top w15: U9_1.7@5687.28,2095 5735,2095 5741.5,2101.5 R62_1.2@5780,2101.5 R58_1.1@5780,2188.5
NetR58_2_1: R58_2.1 R62_2.2 U9_2.7 | length 182.4
  Top w15: U9_2.7@6617.28,2095 6665,2095 6671.5,2101.5 R62_2.2@6710,2101.5 R58_2.1@6710,2188.5
NetR59_1_2: R59_1.2 U10_1.3 | length 236.6
  Top w15: U10_1.3@5687.28,2535 5725,2535 5740,2550 5740,2660 5758.5,2678.5 R59_1.2@5800,2678.5
NetR59_2_2: R59_2.2 U10_2.3 | length 236.6
  Top w15: U10_2.3@6617.28,2535 6655,2535 6670,2550 6670,2660 6688.5,2678.5 R59_2.2@6730,2678.5
NetR65_1_2: R65_1.2 R66_1.2 U10_1.5 | length 395.7
  Top w15: U10_1.5@5472.72,2585 5435,2585 5420,2600 5420,2720 5440,2740 R65_1.2@5548.5,2740 R66_1.2@5548.5,2820
NetR65_2_2: R65_2.2 R66_2.2 U10_2.5 | length 395.7
  Top w15: U10_2.5@6402.72,2585 6365,2585 6350,2600 6350,2720 6370,2740 R65_2.2@6478.5,2740 R66_2.2@6478.5,2820
NetR67_2: R67.2 R79.1 U11.13 | length 496.2
  Top w15: R67.2@7960,2760 8030,2760 8030,2818.5 ; 8030,2820 8050,2840 8292.35,2840 8325.71,2873.36 U11.13@8325.71,2923.23
NetR70_2: R70.2 U12.13 | length 355.6
  Top w15: R70.2@8100,1010 8100,1068.5 ; 8100,1070 8120,1090 8290,1090 8326.02,1126.02 U12.13@8326.02,1173.86
NetR72_2: R72.2 U11.20 | length 154.2
  Top w15: U11.20@8505.16,2913.86 8553.86,2913.86 8580,2940 R72.2@8580,3008.5
NetR73_2: R73.2 U12.20 | length 150
  Top w15: U12.20@8505.16,1173.86 8563.86,1173.86 8580,1190 R73.2@8580,1258.5
NetR75_2: R75.2 U11.18 | length 383.4
  Top w15: U11.18@8453.66,2923.23 8453.66,2876.34 8510,2820 8700,2820 8720,2800 R75.2@8720,2761.5
NetR76_2: R76.2 U12.18 | length 389.7
  Top w15: U12.18@8453.98,1173.86 8453.98,1116.02 8500,1070 8700,1070 8720,1050 R76.2@8720,1011.5
NetR77_2: R77.2 R78.2 | length 77
  Top w15: R77.2@8040,3001.5 R78.2@8040,3078.5
NetR81_2: R81.2 U11.12 | length 541.4
  Top w15: R81.2@7890,2761.5 7890,2850 7910,2870 8283.95,2870 8299.07,2885.12 8299.07,2912.5 U11.12@8300.43,2913.86
NetR82_2: R82.2 U11.8 | length 199
  Top w15: R82.2@8191.5,3220 8310,3220 8326.02,3203.98 U11.8@8326.02,3146.14
NetR84_2: R84.2 U12.12 | length 409.1
  Top w15: R84.2@8030,1011.5 8030,1100 8050,1120 8280,1120 8300.43,1140.43 U12.12@8300.43,1173.86
OSC_IOM1: J2.2 J4.1 U8_1.9 | length 3107.1
  Inner Top w15: J4.1@5730,3550 5730,3480 5750,3460 6220,3460 6240,3480 J2.2@6240,3550
  Inner Bottom w15: J4.1@5730,3550 5730,3440 5750,3420 6390,3420 6570,3600 6570,4842.5 6560,4852.5 v1(6560,4875) v1@6560,4880
  Bottom w15: v1(6560,4875) 6582.3,4875 6589.8,4867.5 U8_1.9@6680.39,4867.5
OSC_IOM2: J2.1 U8_2.9 | length 4294.8
  Inner Bottom w15: J2.1@6140,3550 6140,3620 6160,3640 6420,3640 6490,3710 6490,7325 v1(6560,7395)
  Bottom w15: v1(6560,7395) 6582.3,7395 6589.8,7387.5 U8_2.9@6680.39,7387.5
OSC_IOP1: J4.2 U8_1.10 | length 2288.5
  Inner Bottom w15: J4.2@5830,3550 5830,3480 5850,3460 6380,3460 6530,3610 6530,4886.54 6558.46,4915 v1(6560,4915)
  Bottom w15: v1(6560,4915) 6582.3,4915 6604.8,4892.5 U8_1.10@6680.39,4892.5
OSC_IOP2: J2.3 J4.3 U8_2.10 | length 5106.7
  Inner Top w15: J4.3@5930,3550 5930,3620 5950,3640 6320,3640 6340,3620 J2.3@6340,3550
  Inner Bottom w15: J4.3@5930,3550 5930,3650 5960,3680 6410,3680 6450,3720 6450,7326.54 6558.46,7435 v1(6560,7435)
  Bottom w15: v1(6560,7435) 6582.3,7435 6604.8,7412.5 U8_2.10@6680.39,7412.5
PVDD: C4.1 C13.1 C42_1.1 C42_2.1 C43_1.1 C43_2.1 C44_1.1 C44_2.1 C45_1.1 C45_2.1 C46_1.1 C46_2.1 C47_1.1 C47_2.1 C48_1.1 C48_2.1 C49_1.1 C49_2.1 C50_1.1 C50_2.1 C51_1.1 C51_2.1 C52_1.1 C52_2.1 C53_1.1 C53_2.1 C108.1 C109.1 C110.1 C112.1 C113.1 C114.1 L10.2 R12.2 R77.1 R96.2 U2.4 U2.5 U3.4 U3.5 U8_1.29 U8_1.30 U8_1.31 U8_1.36 U8_1.37 U8_1.38 U8_2.29 U8_2.30 U8_2.31 U8_2.36 U8_2.37 U8_2.38 | length 2864.9
  Top w15: v1(5340,1300) R12.2@5340,1348.5 ; 7380,3030 7471.5,2938.5 R77.1@8040,2938.5
  Inner Top w15: v1(5340,1300) 5655,1300 v1(5935,1020)
  Inner Top w30: v1(5935,1020) v1(5975,1020) 6414.41,1020 6448.98,1054.57 6580.43,1054.57 v1(6615,1020) v1(6655,1020) 7090,1020 7220,1150 v1(7220,1190)
  other v1: 7280,1170 7340,1190 7200,1250 7360,1250 7220,1310 7340,1310 7280,1330 8825,2055 8865,2055 9115,2055 9155,2055 7280,2090 8825,2095 8865,2095 9115,2095 9155,2095 8310,2100 8350,2100 7220,2110 7340,2110 8825,2135 8865,2135 9115,2135 9155,2135 8310,2140 8350,2140 7200,2170 7360,2170 8310,2180 8350,2180 8310,2220 8350,2220 7220,2230 7340,2230 7280,2250 7280,3010 7220,3030 7340,3030 7200,3090 7360,3090 7220,3150 7340,3150 7280,3170 7260,3230 7300,3230 7340,3230 7380,3230 7260,3270 7300,3270 7340,3270 7380,3270 7258.5,3310 7298.5,3310 7338.5,3310 7378.5,3310 7300,4665 7300,4700 7150,4735 7190,4735 7225,4735 7265,4735 7300,4735 7300,4770 7300,4805 7300,5055 7300,5090 7150,5125 7190,5125 7225,5125 7265,5125 7300,5125 7300,5160 7300,5195 7300,7185 7300,7220 7150,7255 7190,7255 7225,7255 7265,7255 7300,7255 7300,7290 7300,7325 7300,7575 7300,7610 7150,7645 7190,7645 7225,7645 7265,7645 7300,7645 7300,7680 7300,7715
RES: R83.2 U11.14 U12.14 | length 2355.3
  Top w15: R83.2@8100,2760 8100,2788.5 ; 8100,2790 8120,2810 8310,2810 v1(8330,2830) 8351.61,2851.61 U11.14@8351.61,2913.86 ; v1(8350,1100) 8351.61,1101.61 U12.14@8351.61,1173.86
  Inner Bottom w15: v1(8330,2830) 8230,2830 8190,2790 8190,1260 v1(8350,1100)
SS: C94.1 U11.7 U12.7 | length 2496.7
  Top w15: v1(8080,1500) 8310,1500 8351.61,1458.39 U12.7@8351.61,1406.14 U12.7@8350.26,1407.5 ; C94.1@8191.5,3300 8230,3300 8280,3250 8330,3250 8351.61,3228.39 U11.7@8351.61,3146.14
  Inner Bottom w15: v1(8080,1500) 8078.54,3150 8199.84,3271.3 v1(8260,3271.3)
SW-1: C88.2 C96.1 D16.2 L9.1 Q3.4 Q4.4 Q5.3 R75.1 R87.1 | length 1583.7
  Top w30: C88.2@8670,3000 8675,2995 v1(8730,2995) ; v1(8720,2650) R75.1@8720,2698.5 8811.5,2698.5 8990,2520 v1(9770,2520)
  Inner Top w30: v1(8720,2650) 8720,2940 8730,2950 v1(8730,2995)
  other v1: 9810,2520 9850,2520 9890,2520 9930,2520 9770,2560 9810,2560 9850,2560 9890,2560 9930,2560 9770,2840 9810,2840 9850,2840 9890,2840 9930,2840 9770,2880 9810,2880 9850,2880 9890,2880 9930,2880 10030,2950 10070,2950 10110,2950 10150,2950 10190,2950 10030,3130 10070,3130 10110,3130 10150,3130 10190,3130
SW-2: C89.2 C116.1 D21.2 L11.1 Q7.4 Q8.4 Q9.3 R76.1 R97.1 | length 1567.1
  Top w30: C89.2@8670,1250 v1(8730,1250) ; v1(8720,900) R76.1@8720,948.5 8770,948.5 8861.5,1040 9730,1040 v1(9770,1080)
  Inner Top w30: v1(8720,900) 8720,1190 8730,1200 v1(8730,1250)
  other v1: 9810,1080 9850,1080 9890,1080 9930,1080 9770,1120 9810,1120 9850,1120 9890,1120 9930,1120 9770,1400 9810,1400 9850,1400 9890,1400 9930,1400 9770,1440 9810,1440 9850,1440 9890,1440 9930,1440 10030,1510 10070,1510 10110,1510 10150,1510 10190,1510 10030,1690 10070,1690 10110,1690 10150,1690 10190,1690
SYNC: U11.1 U12.8 | length 2397.4
  Top w15: v1(8120,1460) 8310,1460 8326.02,1443.98 U12.8@8326.02,1406.14 ; U11.1@8505.16,3146.14 8506.3,3145 v1(8555,3145)
  Inner Bottom w15: v1(8120,1460) 8120,3105 8160,3145 v1(8555,3145)
UVLO: C91.1 R68.1 R80.2 U11.6 U12.6 | length 2825.7
  Top w15: v1(8040,1540) 8310,1540 8377.2,1472.8 U12.6@8377.2,1406.14 ; U11.6@8377.2,3146.14 8377.2,3246.57 8376.89,3246.89 8381.5,3251.5 C91.1@8381.5,3300 R80.2@8381.5,3370 v1(8381.5,3405) R68.1@8381.5,3440
  Inner Bottom w15: v1(8040,1540) 8040,3220 8225,3405 v1(8381.5,3405)
VCC1: C86.1 D14.2 R67.1 U11.17 | length 1111.3
  Top w15: v1@7960,2651.5 R67.1@7960,2700 ; U11.17@8428.07,2923.23 8428.07,2861.93 8480,2810 C86.1@8480,2767.09 8532.09,2767.09 8540.12,2775.12 D14.2@8580,2775.12 8580.12,2775 v1(8635,2775)
  Inner Top w15: v1(7960,2650) 8085,2775 v1(8635,2775)
VCC2: C87.1 D15.2 R70.1 U12.10 U12.17 | length 1677.7
  Top w15: v1(8100,900) R70.1@8100,948.5 ; v1(8225,1405) 8273.7,1405 U12.10@8274.84,1406.14 ; U12.17@8428.39,1173.86 8428.39,1109.27 8480,1057.65 C87.1@8480,1017.09 8536.59,1017.09 8544.62,1025.12 D15.2@8580,1025.12 8580.12,1025 v1(8640,1025)
  Inner Top w15: v1(8100,900) 8225,1025 v1(8640,1025)
  Inner Bottom w15: v1(8225,1405) 8225,1280 8480,1025 v1(8640,1025)
VIN: C97.1 C98.1 C101.1 C104.1 C105.1 C117.1 C118.1 C121.1 J19.1 J19.2 R68.2 R69.2 R71.2 R88.1 R89.1 R91.2 R98.1 R100.2 | length 5056
  Top w15: v1(8260,3440) R68.2@8318.5,3440 R69.2@8318.5,3510 ; R71.2@8300,1651.5 v1(8300,1710) ; R100.2@8721.5,1530 v1(8780,1530) 8780,1570 9220,2010 v1(10360,2010) ; R91.2@8721.5,3280 v1(8780,3280) 8810,3280 8976.83,3446.83 10356.83,3446.83 v1(10360,3450)
  Inner Top w15: v1(8260,3440) 8420,3280 v1(8780,3280) ; v1(8300,1710) 8480,1530 v1(8780,1530)
  Bottom w20: R89.1@11940,2865 C104.1@12098.5,2865
  other v1: 10650,1710 10690,1710 10730,1710 10850,1710 10890,1710 10930,1710 11570,1710 11610,1710 11650,1710 11770,1710 11810,1710 11850,1710 10650,1750 10690,1750 10730,1750 10850,1750 10890,1750 10930,1750 11570,1750 11610,1750 11650,1750 11770,1750 11810,1750 11850,1750 11210,1780 11250,1780 11290,1780 10650,1790 10690,1790 10730,1790 10850,1790 10890,1790 10930,1790 11570,1790 11610,1790 11650,1790 11770,1790 11810,1790 11850,1790 10650,1830 10690,1830 10730,1830 10850,1830 10890,1830 10930,1830 11570,1830 11610,1830 11650,1830 11770,1830 11810,1830 11850,1830 10650,1870 10690,1870 10730,1870 10850,1870 10890,1870 10930,1870 11570,1870 11610,1870 11650,1870 11770,1870 11810,1870 11850,1870 10360,1975 10395,1975 10430,1975 10465,1975 10500,1975 10395,2010 10430,2010 10465,2010 10500,2010 11470,2065 11510,2065 11565,2065 11605,2065 12101.5,2065 12141.5,2065 12196.5,2065 12236.5,2065 11470,2105 11510,2105 11565,2105 11605,2105 12101.5,2105 12141.5,2105 12195,2105 12235,2105 11565,2145 11605,2145 12101.5,2145 12141.5,2145 11565,2185 11605,2185 12100,2185 12140,2185 11563.5,2225 11603.5,2225 12100,2225 12140,2225 11470,2265 11510,2265 11563.5,2265 11603.5,2265 12100,2265 12140,2265 12195,2265 12235,2265 11468.5,2305 11508.5,2305 11563.5,2305 11603.5,2305 12100,2305 12140,2305 12195,2305 12235,2305 12040,2865 12010,2935 12010,2975 12010,3015 10650,3150 10690,3150 10730,3150 10850,3150 10890,3150 10930,3150 11570,3150 11610,3150 11650,3150 11770,3150 11810,3150 11850,3150 10650,3190 10690,3190 10730,3190 10850,3190 10890,3190 10930,3190 11570,3190 11610,3190 11650,3190 11770,3190 11810,3190 11850,3190 11210,3220 11250,3220 11290,3220 10650,3230 10690,3230 10730,3230 10850,3230 10890,3230 10930,3230 11570,3230 11610,3230 11650,3230 11770,3230 11810,3230 11850,3230 10650,3270 10690,3270 10730,3270 10850,3270 10890,3270 10930,3270 11570,3270 11610,3270 11650,3270 11770,3270 11810,3270 11850,3270 10650,3310 10690,3310 10730,3310 10850,3310 10890,3310 10930,3310 11570,3310 11610,3310 11650,3310 11770,3310 11810,3310 11850,3310 10360,3415 10395,3415 10430,3415 10465,3415 10500,3415 10395,3450 10430,3450 10465,3450 10500,3450
pads on no net: D1.MH1 D1.MH2 D2.MH1 D2.MH2 D20.2 FID1.1 FID2.1 FID3.1 FID4.1 J5_1.M1 J5_1.M2 J5_1.M3 J5_2.M1 J5_2.M2 J5_2.M3 J8_1.M1 J8_1.M2 J8_1.M3 J8_2.M1 J8_2.M2 J8_2.M3 L5_1.3 L5_2.3 L6_1.3 L6_2.3 L7_1.3 L7_2.3 L8_1.3 L8_2.3 L9.3 L11.3 S1.MH1 S1.MH2 U1.1 U4.3 U4.6 U4.7 U12.1

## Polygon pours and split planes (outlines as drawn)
GND on Top "Top-No Net 7" (solid, remove dead copper, pour order 514): 4490,8640 4490,6270 6325,6270 6325,6860 6942.5,6860 6942.5,8035 6325,8035 6325,8640
GND on Top "Top-No Net 5" (solid, pour order 489): 6045,6270 6045,6630 7295,6630 7295,6270
GND on Top "Top-No Net 5" (solid, pour order 491): 6045,8270 6045,8640 7295,8640 7295,8270
NetC65_2_1 on Top "Top-No Net 1" (solid, pour order 453): 7020,7850 7020,7570 7100,7570 7100,7850
NetC55_2_2 on Top "Top-No Net 1" (solid, pour order 452): 7020,7330 7020,7050 7100,7050 7100,7330
NetC55_2_2 on Top "Top-No Net 6" (solid, pour order 478): 7090,7330 7125,7330 7645,6810 7645,6270 7320,6270 7320,6830 7090,7060
NetC65_2_1 on Top "Top-No Net 6" (solid, pour order 481): 7090,7570 7125,7570 7645,8090 7645,8640 7320,8640 7320,8070 7090,7840
NetC54_2_2 on Top "Top-No Net 4" (solid, pour order 470): 7095,7380 7105,7380 7125,7380 7655,6850 7695,6850 7695,7430 7125,7430 7115,7440 7095,7440
NetC64_2_1 on Top "Top-No Net 4" (solid, pour order 472): 7095,7520 7105,7520 7125,7520 7655,8050 7695,8050 7695,7470 7125,7470 7115,7460 7095,7460
NetC54_2_2 on Top "Top-No Net" (solid, remove dead copper, pour order 440): 7030,7440 7020,7430 7020,7390 7030,7380 7100,7380 7100,7440
NetC64_2_1 on Top "Top-No Net" (solid, remove dead copper, pour order 438): 7030,7520 7020,7510 7020,7470 7030,7460 7100,7460 7100,7520
NetC54_2_2 on Top "Top-No Net 3" (solid, remove dead copper, pour order 505): 7690,6850 10040,6850 10040,7430 7690,7430
NetC64_2_1 on Top "Top-No Net 3" (solid, remove dead copper, pour order 506): 7690,7470 10040,7470 10040,8050 7690,8050
NetC65_2_1 on Top "Top-No Net 2" (solid, remove dead copper, pour order 487): 8360,8090 7640,8090 7640,8640 8360,8640
NetC55_2_2 on Top "Top-No Net 2" (solid, remove dead copper, pour order 485): 8360,6270 7640,6270 7640,6810 8360,6810
NetC41_2_1 on Top "Bottom-No Net 1" (solid, remove dead copper, pour order 510): 12290,6270 8400,6270 8400,6810 12290,6810
NetC61_2_1 on Top "Bottom-No Net" (solid, remove dead copper, pour order 501): 12290,6850 12290,7430 10080,7430 10080,6850
NetC74_2_1 on Top "Bottom-No Net 1" (solid, remove dead copper, pour order 512): 12290,8640 8400,8640 8400,8090 12290,8090
NetC68_2_1 on Top "Bottom-No Net" (solid, remove dead copper, pour order 502): 12290,7470 12290,8050 10080,8050 10080,7470
PVDD on Top "Inner Top-No Net 16" (solid, remove dead copper, pour order 466): 7295,6670 7295,6820 6365,6820 6365,6670
PVDD on Top "Inner Top-No Net 16" (solid, remove dead copper, pour order 463): 7295,8075 7295,8225 6365,8225 6365,8075
PVDD on Top "Inner Top-No Net 16" (solid, remove dead copper, pour order 464): 7295,5555 7295,5705 6365,5705 6365,5555
PVDD on Top "Inner Top-No Net 16" (solid, remove dead copper, pour order 465): 7295,4150 7295,4300 6365,4300 6365,4150
GND on Top "Top-No Net 33" (solid, pour order 516): 7010,770 7010,3600 4490,3600 4490,770
NetC10_2 on Top "Top-No Net 32" (solid, pour order 441): 6525,1080 6525,965 6455,965 6455,1005 6495,1005 6495,1080
-12V on Top "Top-No Net 29" (solid, pour order 455): 6750,1465 6600,1465 6580,1485 6580,1680 6670,1680 6670,1545 6690,1525 6750,1525
NetC10_2 on Top "Top-No Net 28" (solid, pour order 456): 6685,1160 6685,1380.08 6699.92,1395 6745,1395 6750,1395 6750,1455 6600,1455 6600,1340 6560,1300 6495,1300 6495,1200 6560,1200 6600,1160
PVDD on Top "Top-No Net 25" (solid, pour order 449): 6495,1165 6570,1165 6575,1165 6595,1145 6685,1145 6685,995 6585,995 6585,1086.54 6571.54,1100 6495,1100
NetC9_1 on Top "Top-No Net 27" (solid, pour order 457): 6485,1100 6350,1100 6350,1265 6350,1540 6440,1540 6440,1345 6485,1300
NetC9_2 on Top "Top-No Net 26" (solid, pour order 443): 6350,1080 6485,1080 6485,1010 6350,1010
GND on Top "Top-No Net 31" (solid, pour order 436): 5845,1080 5815,1080 5815,985 5845,985
GND on Top "Top-No Net 30" (solid, pour order 444): 5910,1300 5815,1300 5815,1200 5910,1200
+12V on Top "Top-No Net 29" (solid, pour order 454): 6070,1470 5920,1470 5900,1490 5900,1685 5990,1685 5990,1550 6010,1530 6070,1530
NetC5_1 on Top "Top-No Net 28" (solid, pour order 458): 6005,1160 6005,1380.08 6019.92,1395 6065,1395 6070,1395 6070,1455 5910,1455 5890,1475 5890,1605 5775,1605 5775,1310 5920,1310 5920,1160
NetC3_1 on Top "Top-No Net 27" (solid, pour order 459): 5805,1100 5670,1100 5670,1265 5590,1345 5590,1605 5760,1605 5760,1310 5805,1265
NetC3_2 on Top "Top-No Net 26" (solid, pour order 442): 5670,1080 5805,1080 5805,1010 5670,1010
PVDD on Top "Top-No Net 25" (solid, pour order 448): 5815,1165 5890,1165 5895,1165 5915,1145 6005,1145 6005,995 5905,995 5905,1086.54 5891.54,1100 5815,1100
